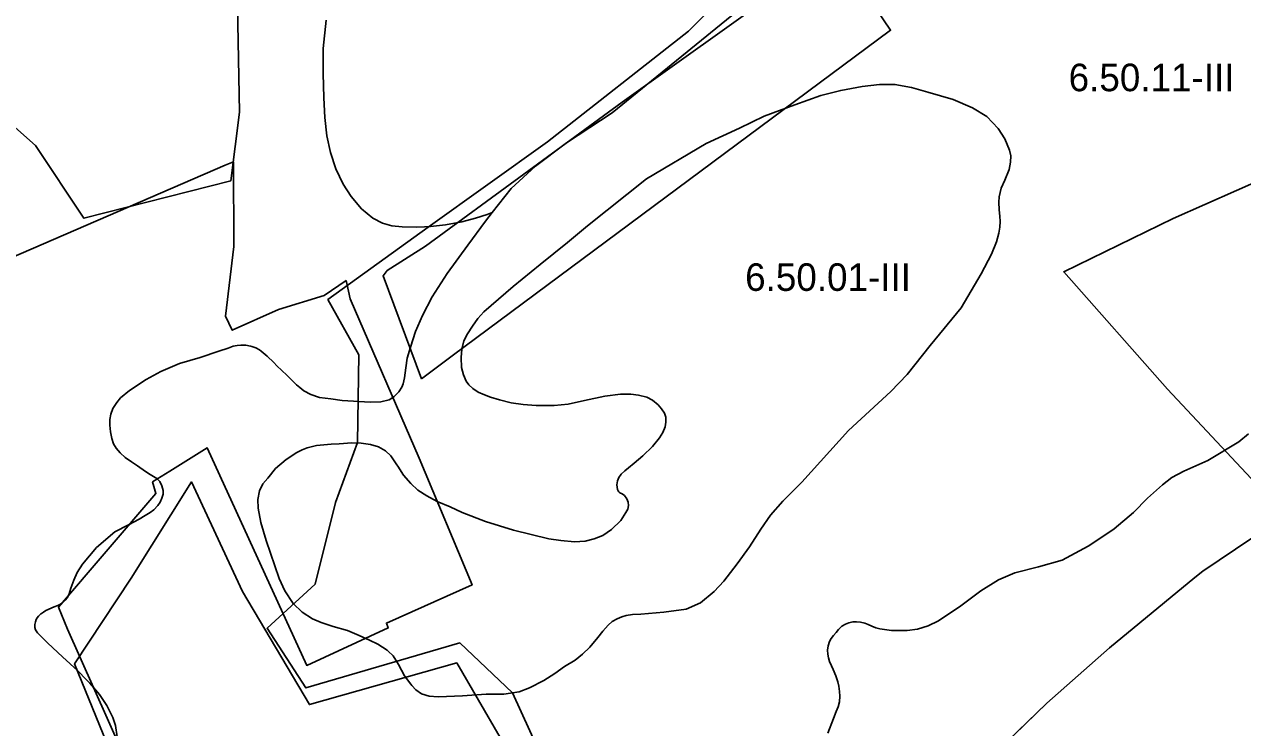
# Model space of a CAD drawing. Extents: x -555156 to -540209, y -1046851 to -1035695.
# Drawn here: x -542588.7 to -542146.3, y -1037687.2 to -1037432 of the extents above; entities that cross this region are included whole.
import ezdxf

# ---------------------------------------------------------------- set-up
doc = ezdxf.new("R2010")
doc.units = 0
for name, color, linetype in [('Vrstva 12', 7, 'Continuous'), ('Vrstva 27', 7, 'Continuous'), ('Vrstva 28', 7, 'Continuous'), ('Vrstva 29', 7, 'Continuous')]:
    doc.layers.add(name, color=color, linetype=linetype)

msp = doc.modelspace()

# ---------------------------------------------------------------- linework, layer by layer
at = {"layer": 'Vrstva 12'}
msp.add_lwpolyline([(-542543.76, -1037717.13), (-542573.06, -1037651.53), (-542576.27, -1037643.56), (-542540.91, -1037602.24), (-542542.14, -1037598.08), (-542535.91, -1037594.17), (-542522.36, -1037585.67), (-542486.16, -1037664.64), (-542456.553705, -1037651.043913), (-542457.22695, -1037649.281052), (-542426.12, -1037635.45), (-542445.33, -1037589.43), (-542470.44, -1037531.64), (-542471.9, -1037524.98), (-542479.81, -1037530.36), (-542496.4, -1037535.52), (-542513.233607, -1037542.9869), (-542515.64, -1037537.9), (-542512.63, -1037512.65), (-542512.77, -1037481.95), (-542515.82, -1037483.08), (-542593.49, -1037516.73)], dxfattribs=at)
at = {"layer": 'Vrstva 28'}
for points in [[(-542418.78, -1037500.25), (-542411.92, -1037491.55), (-542403.15, -1037483.47), (-542391.87, -1037474.97), (-542375.3, -1037464.1), (-542279.87, -1037386.5)], [(-542479.15, -1037430.46), (-542480.14, -1037440.8), (-542480.14, -1037449.87), (-542480, -1037458.66), (-542479.57, -1037465.75), (-542478.86, -1037472.41), (-542477.59, -1037478.5), (-542475.61, -1037484.45), (-542472.91, -1037489.98), (-542470.08, -1037494.52), (-542466.26, -1037498.91), (-542462.15, -1037502.31), (-542458.62, -1037504.11), (-542455.22, -1037505.08), (-542451.49, -1037505.49), (-542446.48, -1037505.65), (-542443.46, -1037505.46), (-542441.21, -1037505.32), (-542435.79, -1037504.76), (-542429.88, -1037503.62), (-542428.01, -1037503.14), (-542424.86, -1037502.33), (-542420.66, -1037501.03), (-542418.78, -1037500.25)], [(-542416.13, -1037568.26), (-542419.41, -1037567.35), (-542421.64, -1037566.49), (-542423.91, -1037565.53), (-542425.91, -1037564.17), (-542427.36, -1037562.8), (-542428.32, -1037561.44), (-542429.24, -1037559.15), (-542429.95, -1037556.53), (-542430.11, -1037552.94), (-542429.87, -1037549.84), (-542429.08, -1037546.89), (-542427.81, -1037544.27), (-542425.98, -1037541.56), (-542423.99, -1037538.7), (-542421.88, -1037536.33), (-542411.15, -1037527.13), (-542401.41, -1037519.19), (-542391.52, -1037511.11), (-542384.16, -1037505.1), (-542362.84, -1037488.04), (-542341.09, -1037475.24), (-542329.01, -1037469.66), (-542320.1, -1037465.34), (-542308.96, -1037461.16), (-542299.49, -1037457.81), (-542292.25, -1037456), (-542284.46, -1037454.61), (-542278.19, -1037453.77), (-542272.62, -1037453.77), (-542266.63, -1037454.89), (-542260.65, -1037456.56), (-542251.46, -1037459.21), (-542244.49, -1037462.27), (-542239.2, -1037465.48), (-542235.17, -1037469.79), (-542232.66, -1037473.56), (-542230.99, -1037477.6), (-542230.55, -1037479.66), (-542230.6, -1037482.02), (-542231.14, -1037484.63), (-542232.65, -1037488.53), (-542234, -1037491.48), (-542234.76, -1037494.54), (-542234.85, -1037496.54), (-542234.76, -1037499.31), (-542234.49, -1037501.63), (-542234.36, -1037503.57), (-542234.45, -1037505.57), (-542234.86, -1037507.75), (-542235.73, -1037510.98), (-542237.5, -1037515.4), (-542241.28, -1037522.52), (-542248.52, -1037534.92), (-542259.79, -1037548.57), (-542268.15, -1037559.02), (-542274.14, -1037565.26)], [(-541720.19, -1037477.06), (-541844.94, -1037500.38), (-541894.08, -1037508.4), (-541898.72, -1037509.58), (-541902.61, -1037510.57), (-541920.68, -1037516.81), (-541947.21, -1037528.47), (-541991.27, -1037545.59), (-542063.6, -1037572.3), (-542092.72, -1037587.26), (-542119.74, -1037602.87), (-542137.04, -1037614.48), (-542160.81, -1037630.43), (-542163.69, -1037632.79), (-542194.71, -1037658.28), (-542217.42, -1037678.3), (-542231.55, -1037691.99)], [(-542229.29, -1037689.8), (-542217.42, -1037678.3), (-542194.71, -1037658.28), (-542163.69, -1037632.79), (-542160.81, -1037630.43), (-542137.04, -1037614.48), (-542119.74, -1037602.87), (-542092.72, -1037587.26), (-542063.6, -1037572.3), (-541991.27, -1037545.59), (-541947.21, -1037528.47), (-541920.68, -1037516.81), (-541902.61, -1037510.57), (-541898.72, -1037509.58), (-541894.08, -1037508.4), (-541844.94, -1037500.38), (-541720.19, -1037477.06)], [(-542418.78, -1037500.25), (-542421.25, -1037503.39), (-542427.68, -1037512.11), (-542435.23, -1037522.45), (-542440.56, -1037530.89), (-542444.15, -1037537.66), (-542446.61, -1037543.47), (-542448.54, -1037549.17), (-542449.66, -1037553.15), (-542450.21, -1037556.65), (-542450.71, -1037560.31), (-542451.18, -1037562.47), (-542451.65, -1037563.72), (-542452.76, -1037565.39), (-542454.44, -1037567.04), (-542454.95, -1037567.38), (-542456.27, -1037568.24), (-542459.21, -1037568.95), (-542463.14, -1037569.15), (-542473.25, -1037568.51), (-542477.36, -1037567.96), (-542481.52, -1037567.4), (-542484.7, -1037566.36), (-542487.17, -1037565.01), (-542488.7, -1037563.79), (-542489.87, -1037562.86), (-542493.38, -1037559.36), (-542497.02, -1037555.87), (-542498.14, -1037554.75), (-542500.48, -1037552.42), (-542502.66, -1037550.6), (-542503.35, -1037550.16), (-542504.59, -1037549.36), (-542506.15, -1037548.89), (-542506.53, -1037548.78), (-542508.3, -1037548.46), (-542510.12, -1037548.41), (-542511.36, -1037548.54), (-542511.48, -1037548.55), (-542512.85, -1037548.82), (-542514.68, -1037549.46), (-542518.02, -1037550.65), (-542524.87, -1037552.9), (-542532.35, -1037555.13), (-542539.19, -1037557.99), (-542544.44, -1037560.94), (-542550.49, -1037564.92), (-542553.82, -1037567.56), (-542555.14, -1037569.2), (-542556.59, -1037571.47), (-542557.28, -1037573.43), (-542557.69, -1037575.38), (-542557.69, -1037577.43), (-542557.41, -1037579.93), (-542556.87, -1037582.34), (-542556.28, -1037584.21), (-542555.37, -1037585.8), (-542553.96, -1037587.48), (-542552.14, -1037589.17), (-542549.73, -1037590.76), (-542547.57, -1037592.27), (-542544.66, -1037594.23), (-542542.95, -1037595.36), (-542542.39, -1037595.73), (-542540.57, -1037596.82), (-542540.28, -1037597.13), (-542539.52, -1037597.96), (-542538.75, -1037599.46), (-542538.3, -1037601.14), (-542538.3, -1037602.51), (-542538.75, -1037603.96), (-542539.43, -1037605.37), (-542540.21, -1037606.65), (-542541.71, -1037608.15), (-542543.03, -1037609.15), (-542544.84, -1037610.29), (-542546.95, -1037611.56), (-542550.9, -1037613.61), (-542555.86, -1037616.18), (-542562.55, -1037621.91), (-542567.56, -1037627.88), (-542569.47, -1037630.98), (-542570.74, -1037633.77), (-542571.77, -1037636.67), (-542572.14, -1037637.77), (-542572.55, -1037638.99), (-542573.09, -1037640.08), (-542573.86, -1037641.03), (-542574.86, -1037641.9), (-542575.82, -1037642.58), (-542576.56, -1037642.89), (-542577.86, -1037643.44), (-542580.87, -1037644.78), (-542581.78, -1037645.3), (-542582.46, -1037645.79), (-542582.68, -1037645.95), (-542583, -1037646.18), (-542583.58, -1037646.83), (-542584.02, -1037647.4)], [(-542274.14, -1037565.26), (-542289.49, -1037579.34), (-542306.4, -1037598.18), (-542313.26, -1037605.08), (-542317.72, -1037610.09), (-542321.34, -1037615.25), (-542325.38, -1037621.66), (-542329.83, -1037627.79), (-542334.7, -1037634.06), (-542338.18, -1037637.79), (-542343.19, -1037641.97), (-542348.34, -1037644.2), (-542356.56, -1037645.31), (-542364.91, -1037646.01), (-542367.9, -1037646.16), (-542370.17, -1037646.48), (-542371.81, -1037647.03), (-542373.4, -1037647.71), (-542375.22, -1037648.71), (-542376.72, -1037650.03), (-542378.63, -1037652.21), (-542380.49, -1037654.49), (-542383.37, -1037658.08), (-542386, -1037660.55), (-542388.7, -1037662.7), (-542392.52, -1037665.08), (-542396.02, -1037667.63), (-542400.08, -1037670.1), (-542405.33, -1037672.81), (-542409.08, -1037674.25), (-542414.65, -1037675.09), (-542421.06, -1037675.09), (-542429.55, -1037675.65), (-542432.45, -1037675.78), (-542435.38, -1037675.92), (-542438.46, -1037676.07), (-542441.7, -1037675.77), (-542444.49, -1037674.97), (-542446.56, -1037673.46), (-542447.96, -1037671.93), (-542448.39, -1037671.47), (-542450.62, -1037668.44), (-542452.84, -1037664.38), (-542454.83, -1037661.2), (-542456.57, -1037659.52), (-542456.98, -1037659.13), (-542460.32, -1037656.9), (-542463.35, -1037655.55), (-542467.09, -1037653.8), (-542471.38, -1037652.04), (-542476.58, -1037650.48), (-542480.87, -1037649.12), (-542484.06, -1037647.69), (-542487.8, -1037645.3), (-542491.06, -1037642.2), (-542494.16, -1037637.58), (-542496.23, -1037633.12), (-542500.85, -1037619.27), (-542502.81, -1037612.81), (-542503.84, -1037607.56), (-542503.92, -1037604.45), (-542503.37, -1037601.27), (-542502.09, -1037598.72), (-542500.34, -1037596.65), (-542497.48, -1037593.15), (-542493.58, -1037589.97), (-542489.76, -1037587.34), (-542487.77, -1037586.45), (-542486.02, -1037585.67), (-542482.6, -1037584.87), (-542479.94, -1037584.59), (-542477.27, -1037584.31), (-542474.33, -1037584.19), (-542469.73, -1037583.82), (-542466.37, -1037584.05), (-542463.05, -1037584.46), (-542460.14, -1037585.37), (-542457.59, -1037586.82), (-542455.64, -1037588.55), (-542453.46, -1037591.87), (-542453.14, -1037592.37), (-542451.05, -1037595.56), (-542448.41, -1037598.67), (-542445.78, -1037601.06), (-542442.52, -1037603.13), (-542438.86, -1037605.12), (-542434.09, -1037607.11), (-542429.71, -1037609.18), (-542421.28, -1037612.4), (-542411.12, -1037615.61), (-542398.25, -1037618.75), (-542393.95, -1037619.31), (-542388.94, -1037619.79), (-542385.04, -1037619.55), (-542381.78, -1037618.75), (-542378.68, -1037617.48), (-542375.5, -1037615.33), (-542372.15, -1037612.06), (-542370.32, -1037609.2)], [(-542370.32, -1037609.2), (-542369.56, -1037607.95), (-542369.29, -1037606.63), (-542369.43, -1037605.45), (-542369.88, -1037604.17), (-542370.84, -1037602.94), (-542371.66, -1037602.35), (-542372.47, -1037601.99), (-542372.86, -1037601.69), (-542373.1, -1037601.35), (-542373.29, -1037600.85), (-542373.52, -1037599.17), (-542373.34, -1037597.67), (-542372.84, -1037596.44), (-542371.97, -1037595.26), (-542370.7, -1037594.07), (-542369.38, -1037592.94), (-542367.29, -1037591.3), (-542364.13, -1037588.61), (-542360.63, -1037585.25), (-542358.08, -1037582.11), (-542356.9, -1037580.11), (-542356.07, -1037578.1), (-542355.8, -1037576.32), (-542355.8, -1037574.5), (-542356.21, -1037573.14), (-542357.3, -1037571.55), (-542358.53, -1037570.09), (-542360.67, -1037568.36), (-542362.71, -1037567.36), (-542365.76, -1037566.63), (-542368.53, -1037566.27), (-542372.23, -1037566.25), (-542377.88, -1037566.89), (-542385.28, -1037568.48), (-542391.24, -1037569.83), (-542396.33, -1037570.31), (-542402.81, -1037570.36), (-542407.59, -1037569.99), (-542411.91, -1037569.4), (-542416.13, -1037568.26)], [(-542286.59, -1037648.81), (-542285.11, -1037648.91), (-542283.5, -1037649.36), (-542282.33, -1037649.77), (-542280.98, -1037650.45), (-542279.58, -1037651.05), (-542278.05, -1037651.38), (-542273.83, -1037652.02), (-542268.18, -1037651.94), (-542264.36, -1037651.46), (-542260.55, -1037650.26), (-542256.77, -1037648.49), (-542248.69, -1037643.06), (-542241.45, -1037637.63), (-542235.05, -1037633.59), (-542229.06, -1037631.08), (-542220.43, -1037628.85), (-542211.93, -1037626.48), (-542202.46, -1037621.33), (-542196.75, -1037617.57), (-542192.95, -1037615.05), (-542186.03, -1037609.16), (-542180.86, -1037603.99), (-542175.45, -1037599.13), (-542172.03, -1037596.43), (-542167.65, -1037594.12), (-542158.98, -1037590.28), (-542147.76, -1037583.51), (-542144.18, -1037580.64)], [(-542584.02, -1037647.4), (-542584.38, -1037648.03), (-542584.67, -1037648.86), (-542584.87, -1037649.77), (-542584.85, -1037650.94), (-542584.64, -1037651.74), (-542583.95, -1037652.81), (-542580.13, -1037656.6), (-542574.8, -1037661.53), (-542569.25, -1037666.67), (-542566.11, -1037669.87), (-542564.87, -1037671.13), (-542561.37, -1037675.27), (-542558.75, -1037679.17), (-542556.52, -1037683.55), (-542555.64, -1037686.41), (-542555.01, -1037690.63), (-542555.41, -1037694.53), (-542555.95, -1037696.67), (-542556.36, -1037698.27)], [(-542296.94, -1037689.24), (-542294.87, -1037683.9), (-542293.92, -1037681.42), (-542293.24, -1037679.74), (-542292.78, -1037677.87), (-542292.64, -1037675.83), (-542292.78, -1037674.1), (-542293.01, -1037672.14), (-542293.37, -1037670.64), (-542294.1, -1037668.46), (-542294.96, -1037666.15), (-542295.66, -1037664.75), (-542296.31, -1037663.29), (-542296.7, -1037661.94), (-542296.96, -1037660.56), (-542297.04, -1037659.13), (-542296.83, -1037657.6), (-542296.31, -1037655.96), (-542295.76, -1037654.89), (-542294.91, -1037653.85), (-542293.95, -1037652.71), (-542293.06, -1037651.62), (-542291.82, -1037650.47), (-542290.52, -1037649.72), (-542289.32, -1037649.2), (-542287.92, -1037648.89), (-542286.59, -1037648.81)]]:
    msp.add_lwpolyline(points, dxfattribs=at)
at = {"layer": 'Vrstva 29'}
for points in [[(-542605.067993, -1037457.986023), (-542584.685913, -1037476.010986), (-542567.09198, -1037502.396912), (-542513.768982, -1037488.814026), (-542510.546997, -1037463.888), (-542511.348999, -1037425.443909), (-542515.911987, -1037390.642029), (-542516.64801, -1037347.348022), (-542512.632019, -1037302.83197), (-542546.349976, -1037300.088989), (-542570.695007, -1037293.862), (-542580.500977, -1037286.677979), (-542629.40802, -1037226.625977)], [(-542444.48, -1037560.59), (-542458.41, -1037523.27), (-542456.95, -1037521.33), (-542443.05, -1037512.44), (-542371.62, -1037460.23), (-542293.97, -1037404.67), (-542250.85, -1037371.22), (-542202.69, -1037339.73), (-542192.28, -1037354.72), (-542283.67, -1037420.07), (-542274.19, -1037434.15), (-542433.32, -1037552.31), (-542444.48, -1037560.59)], [(-542313.831995, -1037400.424008), (-542347.578009, -1037434.492004), (-542398.690004, -1037474.670992), (-542442.039009, -1037505.549005), (-542478.448996, -1037531.886005), (-542467.261992, -1037551.883008), (-542467.729999, -1037583.783993), (-542475.699006, -1037605.588008), (-542483.053998, -1037635.133998), (-542500.579009, -1037651.194995), (-542486.513008, -1037672.813992), (-542430.558996, -1037656.478), (-542411.469992, -1037674.604998), (-542398.272999, -1037703.534007)], [(-541821.079003, -1037415.468001), (-541870.693001, -1037432.305008), (-541904.918995, -1037444.584995), (-541929.102006, -1037464.965997), (-541943.507008, -1037517.192009), (-541957.790997, -1037568.410005), (-541960.511001, -1037608.478995), (-541958.379999, -1037652.962001), (-541963.920004, -1037680.168008), (-541983.566991, -1037694.698001), (-542014.476998, -1037702.771996), (-542036.440006, -1037704.500009), (-542089.766994, -1037670.784994), (-542134.328004, -1037606.414007), (-542173.612991, -1037564.402994), (-542211.293998, -1037521.816995), (-542171.624994, -1037502.516008), (-542091.103991, -1037466.867001), (-542014.463, -1037435.867993), (-541935.387997, -1037405.927008)], [(-542408.104004, -1037704.406982), (-542431.680969, -1037663.757996), (-542485.184021, -1037678.853027), (-542509.487976, -1037637.861023), (-542528.046997, -1037598.067017), (-542549.870972, -1037633.046021), (-542570.458008, -1037664.081909), (-542549.655029, -1037715.137024)]]:
    msp.add_lwpolyline(points, dxfattribs=at)

# ---------------------------------------------------------------- texts
at = {"layer": 'Vrstva 27'}
for s, p in [('6.50.11-III', (-542209.526548, -1037456.27)), ('6.50.01-III', (-542326.986548, -1037528.73))]:
    msp.add_text(s, height=10, dxfattribs=at).set_placement(p)

doc.saveas('drawing.dxf')
